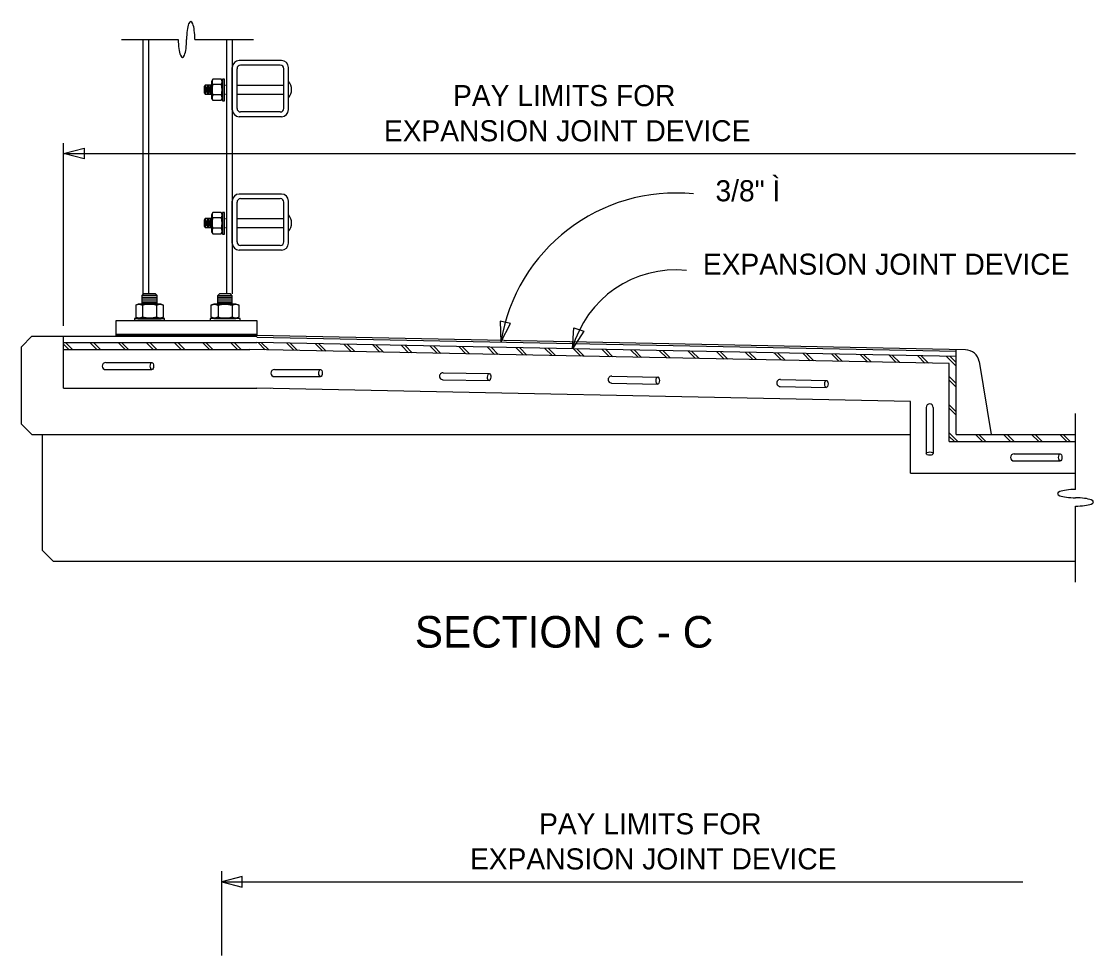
# Model space of a CAD drawing. Extents: x 19590 to 20151, y 19944 to 20103.
# Drawn here: x 19649.5 to 19673.02, y 20040.33 to 20060.83 of the extents above; entities that cross this region are included whole.
import ezdxf

# ---------------------------------------------------------------- set-up
doc = ezdxf.new("R2010")
doc.units = 0
for name, color, linetype in [('DETAIL_PR', 7, 'Continuous'), ('DETAIL_TEXT_DIMEN_PR', 7, 'Continuous'), ('Level 1', 7, 'Continuous'), ('Sheet_Label_Str_Wt0', 7, 'Continuous')]:
    doc.layers.add(name, color=color, linetype=linetype)

msp = doc.modelspace()

# ---------------------------------------------------------------- linework, layer by layer
at = {"layer": 'DETAIL_PR'}
for p, q in [((19651.701, 20060.437), (19652.944, 20060.437)), ((19652.164, 20060.437), (19652.164, 20054.856)), ((19652.291, 20060.437), (19652.291, 20054.856)), ((19653.308, 20060.437), (19654.592, 20060.437)), ((19654.002, 20060.437), (19654.002, 20054.854)), ((19654.129, 20060.437), (19654.129, 20054.854)), ((19654.129, 20058.895), (19654.129, 20059.82)), ((19654.232, 20058.922), (19654.232, 20059.794)), ((19655.208, 20059.975), (19654.283, 20059.975)), ((19655.182, 20059.871), (19654.309, 20059.871)), ((19655.259, 20058.922), (19655.259, 20059.794)), ((19655.361, 20058.895), (19655.361, 20059.82)), ((19653.537, 20059.434), (19653.537, 20059.239)), ((19653.564, 20059.395), (19653.564, 20059.276)), ((19653.578, 20059.434), (19653.578, 20059.239)), ((19653.592, 20059.395), (19653.592, 20059.276)), ((19653.604, 20059.434), (19653.604, 20059.239)), ((19653.625, 20059.395), (19653.625, 20059.276)), ((19653.645, 20059.434), (19653.645, 20059.239)), ((19653.658, 20059.395), (19653.658, 20059.276)), ((19653.888, 20059.448), (19653.699, 20059.448)), ((19653.955, 20059.434), (19653.982, 20059.434)), ((19654.232, 20059.433), (19655.259, 20059.433)), ((19653.888, 20059.223), (19653.699, 20059.223)), ((19653.955, 20059.238), (19653.982, 20059.238)), ((19654.232, 20059.238), (19655.259, 20059.238)), ((19655.182, 20058.845), (19654.309, 20058.845)), ((19655.208, 20058.742), (19654.283, 20058.742)), ((19655.208, 20057.045), (19654.283, 20057.045)), ((19654.129, 20055.966), (19654.129, 20056.891)), ((19654.232, 20055.993), (19654.232, 20056.865)), ((19655.182, 20056.942), (19654.309, 20056.942)), ((19655.259, 20055.993), (19655.259, 20056.865)), ((19655.361, 20055.966), (19655.361, 20056.891)), ((19653.537, 20056.504), (19653.537, 20056.31)), ((19653.578, 20056.504), (19653.578, 20056.31)), ((19653.604, 20056.504), (19653.604, 20056.31)), ((19653.645, 20056.504), (19653.645, 20056.31)), ((19653.888, 20056.519), (19653.699, 20056.519)), ((19653.955, 20056.504), (19653.982, 20056.504)), ((19654.232, 20056.504), (19655.259, 20056.504)), ((19653.564, 20056.466), (19653.564, 20056.347)), ((19653.592, 20056.466), (19653.592, 20056.347)), ((19653.625, 20056.466), (19653.625, 20056.347)), ((19653.658, 20056.466), (19653.658, 20056.347)), ((19653.888, 20056.294), (19653.699, 20056.294)), ((19653.955, 20056.309), (19653.982, 20056.309)), ((19654.232, 20056.309), (19655.259, 20056.309)), ((19655.208, 20055.813), (19654.283, 20055.813)), ((19655.182, 20055.915), (19654.309, 20055.915)), ((19652.481, 20054.817), (19652.145, 20054.817)), ((19652.481, 20054.777), (19652.145, 20054.777)), ((19652.481, 20054.737), (19652.145, 20054.737)), ((19652.481, 20054.697), (19652.145, 20054.697)), ((19652.481, 20054.658), (19652.145, 20054.658)), ((19654.128, 20054.814), (19653.805, 20054.814)), ((19654.128, 20054.775), (19653.805, 20054.775)), ((19654.128, 20054.735), (19653.805, 20054.735)), ((19654.128, 20054.695), (19653.805, 20054.695)), ((19654.128, 20054.655), (19653.805, 20054.655)), ((19652.158, 20054.604), (19652.158, 20054.352)), ((19652.467, 20054.604), (19652.467, 20054.352)), ((19653.819, 20054.602), (19653.819, 20054.35)), ((19654.128, 20054.602), (19654.128, 20054.35)), ((19649.734, 20053.924), (19649.503, 20053.692)), ((19649.734, 20053.924), (19654.668, 20053.924)), ((19650.428, 20052.781), (19650.428, 20053.924)), ((19670.214, 20053.627), (19654.668, 20053.938)), ((19649.503, 20051.997), (19649.503, 20053.692)), ((19650.428, 20053.786), (19654.668, 20053.786)), ((19650.544, 20053.632), (19650.428, 20053.748)), ((19650.621, 20053.632), (19650.467, 20053.786)), ((19651.16, 20053.632), (19651.006, 20053.786)), ((19651.237, 20053.632), (19651.083, 20053.786)), ((19651.777, 20053.632), (19651.623, 20053.786)), ((19651.854, 20053.632), (19651.7, 20053.786)), ((19652.394, 20053.632), (19652.24, 20053.786)), ((19652.471, 20053.632), (19652.317, 20053.786)), ((19653.01, 20053.632), (19652.856, 20053.786)), ((19653.087, 20053.632), (19652.933, 20053.786)), ((19653.627, 20053.632), (19653.473, 20053.786)), ((19653.704, 20053.632), (19653.55, 20053.786)), ((19654.244, 20053.632), (19654.09, 20053.786)), ((19654.321, 20053.632), (19654.167, 20053.786)), ((19670.007, 20053.592), (19654.668, 20053.899)), ((19670.007, 20053.477), (19654.668, 20053.783)), ((19654.85, 20053.626), (19654.693, 20053.783)), ((19654.929, 20053.624), (19654.771, 20053.781)), ((19655.477, 20053.615), (19655.323, 20053.769)), ((19655.558, 20053.611), (19655.401, 20053.769)), ((19656.109, 20053.6), (19655.951, 20053.758)), ((19656.187, 20053.599), (19656.03, 20053.756)), ((19656.738, 20053.588), (19656.581, 20053.745)), ((19656.817, 20053.586), (19656.659, 20053.744)), ((19657.367, 20053.575), (19657.21, 20053.733)), ((19657.446, 20053.574), (19657.288, 20053.731)), ((19657.996, 20053.563), (19657.839, 20053.72)), ((19658.075, 20053.561), (19657.918, 20053.718)), ((19658.626, 20053.55), (19658.468, 20053.707)), ((19658.704, 20053.548), (19658.547, 20053.706)), ((19659.255, 20053.537), (19659.098, 20053.695)), ((19659.334, 20053.536), (19659.176, 20053.693)), ((19659.884, 20053.525), (19659.727, 20053.682)), ((19659.963, 20053.523), (19659.805, 20053.681)), ((19650.428, 20053.632), (19654.514, 20053.632)), ((19669.853, 20053.325), (19654.514, 20053.632)), ((19660.513, 20053.512), (19660.356, 20053.67)), ((19660.592, 20053.511), (19660.435, 20053.668)), ((19661.143, 20053.5), (19660.985, 20053.657)), ((19661.221, 20053.498), (19661.064, 20053.655)), ((19661.772, 20053.487), (19661.615, 20053.644)), ((19661.851, 20053.485), (19661.693, 20053.643)), ((19662.401, 20053.474), (19662.244, 20053.632)), ((19662.48, 20053.473), (19662.322, 20053.63)), ((19663.03, 20053.462), (19662.873, 20053.619)), ((19663.109, 20053.46), (19662.952, 20053.618)), ((19663.66, 20053.449), (19663.502, 20053.607)), ((19663.738, 20053.448), (19663.581, 20053.605)), ((19664.289, 20053.437), (19664.132, 20053.594)), ((19664.368, 20053.435), (19664.21, 20053.592)), ((19664.918, 20053.424), (19664.761, 20053.581)), ((19664.997, 20053.423), (19664.84, 20053.58)), ((19665.547, 20053.412), (19665.39, 20053.569)), ((19665.626, 20053.41), (19665.469, 20053.567)), ((19666.177, 20053.399), (19666.019, 20053.556)), ((19666.255, 20053.397), (19666.098, 20053.555)), ((19666.806, 20053.386), (19666.649, 20053.544)), ((19666.885, 20053.385), (19666.727, 20053.542)), ((19667.435, 20053.374), (19667.278, 20053.531)), ((19667.514, 20053.372), (19667.357, 20053.53)), ((19668.064, 20053.361), (19667.907, 20053.519)), ((19668.143, 20053.36), (19667.986, 20053.517)), ((19668.694, 20053.349), (19668.536, 20053.506)), ((19668.774, 20053.346), (19668.615, 20053.504)), ((19669.323, 20053.336), (19669.166, 20053.493)), ((19669.402, 20053.334), (19669.244, 20053.492)), ((19670.007, 20053.268), (19669.795, 20053.481)), ((19670.007, 20053.346), (19669.874, 20053.479)), ((19670.007, 20051.765), (19670.007, 20053.631)), ((19651.353, 20053.345), (19652.364, 20053.345)), ((19669.853, 20051.611), (19669.853, 20053.325)), ((19670.512, 20053.369), (19670.778, 20051.765)), ((19651.353, 20053.191), (19652.364, 20053.191)), ((19655.053, 20053.191), (19656.064, 20053.191)), ((19655.053, 20053.037), (19656.064, 20053.037)), ((19658.751, 20052.969), (19659.762, 20052.949)), ((19658.754, 20053.123), (19659.765, 20053.103)), ((19662.453, 20053.049), (19663.464, 20053.029)), ((19666.152, 20052.975), (19667.164, 20052.955)), ((19670.007, 20052.883), (19669.853, 20053.037)), ((19650.428, 20052.781), (19654.668, 20052.781)), ((19669.005, 20052.494), (19654.668, 20052.781)), ((19654.976, 20052.775), (19654.668, 20052.781)), ((19662.45, 20052.895), (19663.461, 20052.875)), ((19666.149, 20052.821), (19667.161, 20052.801)), ((19670.007, 20052.806), (19669.853, 20052.96)), ((19669.005, 20050.917), (19669.005, 20052.494)), ((19669.352, 20052.361), (19669.352, 20051.348)), ((19669.352, 20052.361), (19669.352, 20051.502)), ((19669.506, 20052.361), (19669.506, 20051.348)), ((19669.506, 20052.361), (19669.506, 20051.502)), ((19670.007, 20052.266), (19669.853, 20052.421)), ((19670.007, 20052.189), (19669.853, 20052.343)), ((19672.628, 20050.56), (19672.628, 20052.228)), ((19649.734, 20051.765), (19649.503, 20051.997)), ((19670.046, 20051.611), (19669.853, 20051.804)), ((19649.734, 20051.765), (19669.005, 20051.765)), ((19649.966, 20049.222), (19649.966, 20051.765)), ((19669.969, 20051.611), (19669.853, 20051.727)), ((19669.853, 20051.611), (19672.628, 20051.611)), ((19670.007, 20051.765), (19672.628, 20051.765)), ((19670.585, 20051.611), (19670.431, 20051.765)), ((19670.662, 20051.611), (19670.508, 20051.765)), ((19671.202, 20051.611), (19671.048, 20051.765)), ((19671.279, 20051.611), (19671.125, 20051.765)), ((19671.819, 20051.611), (19671.665, 20051.765)), ((19671.896, 20051.611), (19671.742, 20051.765)), ((19672.435, 20051.611), (19672.281, 20051.765)), ((19672.512, 20051.611), (19672.358, 20051.765)), ((19671.279, 20051.341), (19672.291, 20051.341)), ((19671.279, 20051.187), (19672.291, 20051.187)), ((19669.005, 20050.917), (19672.628, 20050.917)), ((19672.628, 20048.528), (19672.628, 20050.196)), ((19649.966, 20049.222), (19650.197, 20048.99)), ((19650.197, 20048.99), (19672.628, 20048.99))]:
    msp.add_line(p, q, dxfattribs=at)
for points in [[(19653.699, 20059.568), (19653.672, 20059.515), (19653.672, 20059.143), (19653.699, 20059.104), (19653.888, 20059.104), (19653.914, 20059.143), (19653.914, 20059.515), (19653.888, 20059.568), (19653.699, 20059.568)], [(19653.914, 20059.568), (19653.914, 20059.09), (19653.955, 20059.09), (19653.955, 20059.568), (19653.914, 20059.568)], [(19653.672, 20059.434), (19653.537, 20059.434), (19653.51, 20059.403), (19653.51, 20059.269), (19653.537, 20059.239), (19653.672, 20059.239)], [(19653.672, 20056.504), (19653.537, 20056.504), (19653.51, 20056.474), (19653.51, 20056.34), (19653.537, 20056.31), (19653.672, 20056.31)], [(19653.699, 20056.639), (19653.672, 20056.586), (19653.672, 20056.214), (19653.699, 20056.174), (19653.888, 20056.174), (19653.914, 20056.214), (19653.914, 20056.586), (19653.888, 20056.639), (19653.699, 20056.639)], [(19653.914, 20056.639), (19653.914, 20056.161), (19653.955, 20056.161), (19653.955, 20056.639), (19653.914, 20056.639)], [(19652.481, 20054.631), (19652.481, 20054.817), (19652.441, 20054.856), (19652.184, 20054.856), (19652.145, 20054.817), (19652.145, 20054.631)], [(19654.128, 20054.629), (19654.128, 20054.814), (19654.088, 20054.854), (19653.846, 20054.854), (19653.805, 20054.814), (19653.805, 20054.629)], [(19652.064, 20054.312), (19652.561, 20054.312), (19652.616, 20054.352), (19652.616, 20054.604), (19652.561, 20054.631), (19652.064, 20054.631), (19652.01, 20054.604), (19652.01, 20054.352), (19652.064, 20054.312)], [(19653.725, 20054.31), (19654.209, 20054.31), (19654.277, 20054.35), (19654.277, 20054.602), (19654.209, 20054.629), (19653.725, 20054.629), (19653.657, 20054.602), (19653.657, 20054.35), (19653.725, 20054.31)], [(19652.642, 20054.312), (19651.983, 20054.312), (19651.983, 20054.273), (19652.642, 20054.273), (19652.642, 20054.312)], [(19654.303, 20054.31), (19653.644, 20054.31), (19653.644, 20054.27), (19654.303, 20054.27), (19654.303, 20054.31)]]:
    msp.add_lwpolyline(points, dxfattribs=at)
for points in [[(19654.668, 20053.962), (19651.584, 20053.962), (19651.584, 20054.271), (19654.668, 20054.271)], [(19651.584, 20053.962), (19654.668, 20053.962), (19654.668, 20053.924), (19651.584, 20053.924)]]:
    msp.add_lwpolyline(points, close=True, dxfattribs=at)
for centre, radius, start, end in [((19654.283, 20059.82), 0.154, 90, 180), ((19654.309, 20059.795), 0.077, 90, 180), ((19655.182, 20059.795), 0.077, 0, 90), ((19655.207, 20059.82), 0.154, 0, 90), ((19655.154, 20059.336), 0.275, 319.1029, 40.8971), ((19654.283, 20058.896), 0.154, 180, 270), ((19654.309, 20058.922), 0.077, 180, 270), ((19655.182, 20058.922), 0.077, 270, 360), ((19655.207, 20058.896), 0.154, 270, 360), ((19654.283, 20056.891), 0.154, 90, 180), ((19655.207, 20056.891), 0.154, 0, 90), ((19654.309, 20056.866), 0.077, 90, 180), ((19655.182, 20056.866), 0.077, 0, 90), ((19655.154, 20056.407), 0.275, 319.1029, 40.8971), ((19654.283, 20055.967), 0.154, 180, 270), ((19654.309, 20055.993), 0.077, 180, 270), ((19655.182, 20055.993), 0.077, 270, 360), ((19655.207, 20055.967), 0.154, 270, 360), ((19670.208, 20053.318), 0.308, 9.4315, 88.8542), ((19651.353, 20053.268), 0.0771, 90, 270), ((19655.053, 20053.114), 0.0771, 90, 270), ((19658.752, 20053.046), 0.0771, 88.8543, 268.8543), ((19662.452, 20052.972), 0.0771, 88.8543, 268.8543), ((19666.151, 20052.898), 0.0771, 88.8543, 268.8543), ((19669.429, 20052.361), 0.0771, 0, 180), ((19671.279, 20051.264), 0.0771, 90, 270)]:
    msp.add_arc(centre, radius, start, end, dxfattribs=at)
for centre, major_axis, ratio, start_param, end_param in [((19653.217, 20060.437), (0, -0.395), 0.230204, 1.570796, 4.712389), ((19653.035, 20060.437), (0, -0.395), 0.230206, 4.712389, 7.853982), ((19653.789, 20059.51), (0.105, 0), 0.985841, 2.541474, 3.741711), ((19653.802, 20059.51), (0.105, 0), 0.985841, 5.683067, 6.883304), ((19654.076, 20059.334), (0.392, 0), 0.985841, 2.834625, 3.44856), ((19653.515, 20059.334), (0.392, 0), 0.985841, 5.976218, 6.590153), ((19653.789, 20059.159), (0.105, 0), 0.985841, 2.541474, 3.741711), ((19653.802, 20059.159), (0.105, 0), 0.985841, 5.683067, 6.883304), ((19653.789, 20056.58), (0.105, 0), 0.985841, 2.541474, 3.741711), ((19654.076, 20056.405), (0.392, 0), 0.985841, 2.834625, 3.44856), ((19653.802, 20056.58), (0.105, 0), 0.985841, 5.683067, 6.883304), ((19653.515, 20056.405), (0.392, 0), 0.985841, 5.976218, 6.590153), ((19653.789, 20056.23), (0.105, 0), 0.985841, 2.541474, 3.741711), ((19653.802, 20056.23), (0.105, 0), 0.985841, 5.683067, 6.883304), ((19652.083, 20054.488), (0.136, 0), 0.985841, 0.970676, 2.170917), ((19652.314, 20054.12), (0.51, 0), 0.985841, 1.263828, 1.877765), ((19652.545, 20054.488), (0.136, 0), 0.985841, 0.970677, 2.170916), ((19653.738, 20054.486), (0.136, 0), 0.985841, 0.970676, 2.170917), ((19653.969, 20054.118), (0.51, 0), 0.985841, 1.263828, 1.877765), ((19654.201, 20054.486), (0.136, 0), 0.985841, 0.970677, 2.170916), ((19652.083, 20054.462), (0.136, 0), 0.985841, 4.112273, 5.312505), ((19652.314, 20054.83), (0.51, 0), 0.985841, 4.405422, 5.019356), ((19652.545, 20054.462), (0.136, 0), 0.985841, 4.112272, 5.312505), ((19653.738, 20054.46), (0.136, 0), 0.985841, 4.112273, 5.312505), ((19653.969, 20054.828), (0.51, 0), 0.985841, 4.405422, 5.019356), ((19654.201, 20054.46), (0.136, 0), 0.985841, 4.112272, 5.312505), ((19672.628, 20050.469), (0.395, 0), 0.230204, 1.570796, 4.712389), ((19672.628, 20050.287), (0.395, 0), 0.230206, 4.712389, 7.853982)]:
    msp.add_ellipse(centre, major_axis=major_axis, ratio=ratio, start_param=start_param, end_param=end_param, dxfattribs=at)
for centre, major_axis in [((19652.364, 20053.268), (0, 0.0773)), ((19656.064, 20053.114), (0, 0.0773)), ((19659.764, 20053.026), (0.0015, 0.0773)), ((19663.463, 20052.952), (0.0015, 0.0773)), ((19667.162, 20052.878), (0.0015, 0.0773)), ((19669.429, 20051.348), (0.0773, 0)), ((19672.291, 20051.264), (0, 0.0773))]:
    msp.add_ellipse(centre, major_axis=major_axis, ratio=0.466726, dxfattribs=at)
at = {"layer": 'DETAIL_TEXT_DIMEN_PR'}
for p, q in [((19650.428, 20054.155), (19650.428, 20058.163)), ((19650.428, 20057.932), (19672.628, 20057.932)), ((19653.896, 20040.332), (19653.896, 20042.182)), ((19653.896, 20041.951), (19671.471, 20041.951))]:
    msp.add_line(p, q, dxfattribs=at)
for centre, radius, end in [((19663.854, 20053.187), 3.879, 171.0299), ((19663.854, 20053.033), 2.347, 164.8834)]:
    msp.add_arc(centre, radius, 84.1624, end, dxfattribs=at)
at = {"layer": 'Level 1'}
for p, q in [((19650.428, 20057.932), (19650.876, 20058.048)), ((19650.876, 20057.816), (19650.428, 20057.932)), ((19650.876, 20058.048), (19650.876, 20057.816)), ((19660.234, 20054.203), (19660.008, 20054.254)), ((19660.008, 20054.254), (19660.023, 20053.792)), ((19660.023, 20053.792), (19660.234, 20054.203)), ((19661.589, 20053.645), (19661.623, 20054.106)), ((19661.842, 20054.032), (19661.589, 20053.645)), ((19661.623, 20054.106), (19661.842, 20054.032)), ((19654.344, 20042.067), (19653.896, 20041.951)), ((19653.896, 20041.951), (19654.344, 20041.835)), ((19654.344, 20041.835), (19654.344, 20042.067))]:
    msp.add_line(p, q, dxfattribs=at)

# ---------------------------------------------------------------- texts
at = {"layer": 'DETAIL_TEXT_DIMEN_PR'}
for s, height, p in [('PAY LIMITS FOR', 0.4625, (19658.971, 20058.973)), ('EXPANSION JOINT DEVICE', 0.4625, (19657.454, 20058.202)), ('EXPANSION JOINT DEVICE', 0.4625, (19664.452, 20055.273)), ('SECTION C - C', 0.69385, (19658.133, 20047.09)), ('PAY LIMITS FOR', 0.4625, (19660.859, 20042.992)), ('EXPANSION JOINT DEVICE', 0.4625, (19659.342, 20042.222))]:
    msp.add_text(s, height=height, dxfattribs=at).set_placement(p)
at = {"layer": 'Sheet_Label_Str_Wt0'}
msp.add_text('3/8" Ì', height=0.4625, dxfattribs=at).set_placement((19664.729, 20056.885))

doc.saveas('drawing.dxf')
